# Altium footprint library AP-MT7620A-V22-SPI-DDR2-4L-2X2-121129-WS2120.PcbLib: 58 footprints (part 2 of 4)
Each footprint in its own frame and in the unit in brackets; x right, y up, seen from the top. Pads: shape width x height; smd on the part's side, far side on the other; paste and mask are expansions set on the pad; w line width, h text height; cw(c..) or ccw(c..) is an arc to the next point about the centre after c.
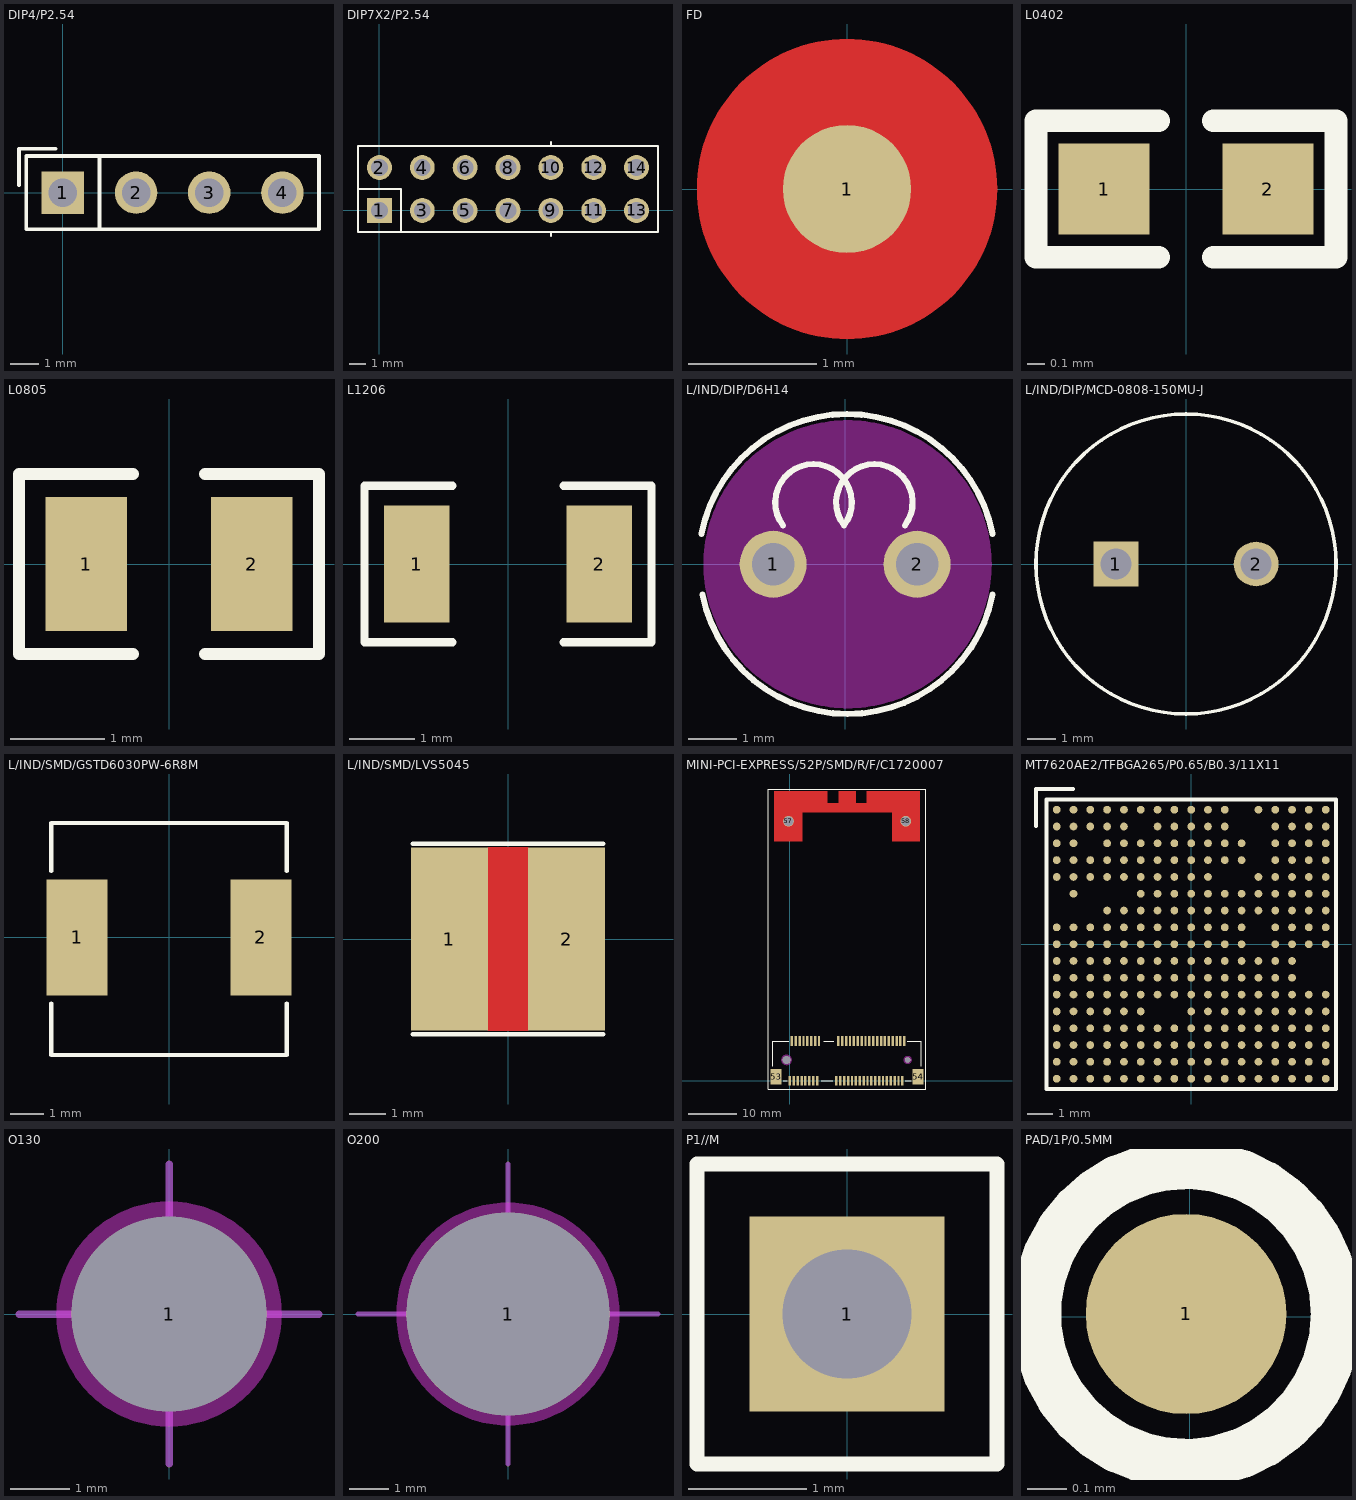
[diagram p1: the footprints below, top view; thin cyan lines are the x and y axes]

## DIP4/P2.54 [mil]
pads (4):
  rect 58x58 hole 39: 1(0,0)
  round 58 hole 39: 2(100,0) 3(200,0) 4(300,0)
Top Overlay:
  lines w5: -60,10 -60,60 -10,60 ; 50,-50 50,50 ; -50,-50 350,-50 350,50 -50,50 -50,-50

## DIP7X2/P2.54 [mil]
pads (14):
  rect 58x58 hole 39: 1(0,0)
  round 58 hole 39: 2(0,100) 3(100,0) 4(100,100) 5(200,0) 6(200,100) 7(300,0) 8(300,100) 9(400,0) 10(400,100) 11(500,0) 12(500,100) 13(600,0) 14(600,100)
Top Overlay:
  lines w5: -50,50 50,50 50,-50 ; 400,-60 400,-50 ; 400,150 400,160 ; -50,-50 650,-50 650,150 -50,150 -50,-50

## FD [mm]
pads (1):
  round 1 smd: 1(0,0)
Top Layer:
  pour cut-out: 1.169,0 1.167,0.057 1.163,0.115 1.156,0.171 1.146,0.228 1.134,0.284 1.118,0.339 1.1,0.394 1.08,0.447 1.057,0.5 1.031,0.551 1.002,0.601 0.972,0.649 0.939,0.696 0.903,0.741 0.866,0.785 0.826,0.826 0.785,0.866 0.741,0.903 0.696,0.939 0.649,0.972 0.601,1.002 0.551,1.031 0.5,1.057 0.447,1.08 0.394,1.1 0.339,1.118 0.284,1.134 0.228,1.146 0.171,1.156 0.115,1.163 0.057,1.167 0,1.169 -0.057,1.167 -0.115,1.163 -0.171,1.156 -0.228,1.146 -0.284,1.134 -0.339,1.118 -0.394,1.1 -0.447,1.08 -0.5,1.057 -0.551,1.031 -0.601,1.002 -0.649,0.972 -0.696,0.939 -0.741,0.903 -0.785,0.866 -0.826,0.826 -0.866,0.785 -0.903,0.741 -0.939,0.696 -0.972,0.649 -1.002,0.601 -1.031,0.551 -1.057,0.5 -1.08,0.447 -1.1,0.394 -1.118,0.339 -1.134,0.284 -1.146,0.228 -1.156,0.171 -1.163,0.115 -1.167,0.057 -1.169,0 -1.167,-0.057 -1.163,-0.115 -1.156,-0.171 -1.146,-0.228 -1.134,-0.284 -1.118,-0.339 -1.1,-0.394 -1.08,-0.447 -1.057,-0.5 -1.031,-0.551 -1.002,-0.601 -0.972,-0.649 -0.939,-0.696 -0.903,-0.741 -0.866,-0.785 -0.826,-0.826 -0.785,-0.866 -0.741,-0.903 -0.696,-0.939 -0.649,-0.972 -0.601,-1.002 -0.551,-1.031 -0.5,-1.057 -0.447,-1.08 -0.394,-1.1 -0.339,-1.118 -0.284,-1.134 -0.228,-1.146 -0.171,-1.156 -0.115,-1.163 -0.057,-1.167 0,-1.169 0.057,-1.167 0.115,-1.163 0.171,-1.156 0.228,-1.146 0.284,-1.134 0.339,-1.118 0.394,-1.1 0.447,-1.08 0.5,-1.057 0.551,-1.031 0.601,-1.002 0.649,-0.972 0.696,-0.939 0.741,-0.903 0.785,-0.866 0.826,-0.826 0.866,-0.785 0.903,-0.741 0.939,-0.696 0.972,-0.649 1.002,-0.601 1.031,-0.551 1.057,-0.5 1.08,-0.447 1.1,-0.394 1.118,-0.339 1.134,-0.284 1.146,-0.228 1.156,-0.171 1.163,-0.115 1.167,-0.057
Top Solder:
  region: 1.016,0 1.015,0.053 1.011,0.106 1.004,0.159 0.994,0.211 0.982,0.263 0.967,0.314 0.949,0.364 0.928,0.413 0.906,0.461 0.88,0.508 0.852,0.554 0.822,0.597 0.79,0.64 0.755,0.68 0.719,0.719 0.68,0.755 0.64,0.79 0.597,0.822 0.554,0.852 0.508,0.88 0.461,0.906 0.413,0.928 0.364,0.949 0.314,0.967 0.263,0.982 0.211,0.994 0.159,1.004 0.106,1.011 0.053,1.015 0,1.016 -0.053,1.015 -0.106,1.011 -0.159,1.004 -0.211,0.994 -0.263,0.982 -0.314,0.967 -0.364,0.949 -0.413,0.928 -0.461,0.906 -0.508,0.88 -0.554,0.852 -0.597,0.822 -0.64,0.79 -0.68,0.755 -0.719,0.719 -0.755,0.68 -0.79,0.64 -0.822,0.597 -0.852,0.554 -0.88,0.508 -0.906,0.461 -0.928,0.413 -0.949,0.364 -0.967,0.314 -0.982,0.263 -0.994,0.211 -1.004,0.159 -1.011,0.106 -1.015,0.053 -1.016,0 -1.015,-0.053 -1.011,-0.106 -1.004,-0.159 -0.994,-0.211 -0.982,-0.263 -0.967,-0.314 -0.949,-0.364 -0.928,-0.413 -0.906,-0.461 -0.88,-0.508 -0.852,-0.554 -0.822,-0.597 -0.79,-0.64 -0.755,-0.68 -0.719,-0.719 -0.68,-0.755 -0.64,-0.79 -0.597,-0.822 -0.554,-0.852 -0.508,-0.88 -0.461,-0.906 -0.413,-0.928 -0.364,-0.949 -0.314,-0.967 -0.263,-0.982 -0.211,-0.994 -0.159,-1.004 -0.106,-1.011 -0.053,-1.015 0,-1.016 0.053,-1.015 0.106,-1.011 0.159,-1.004 0.211,-0.994 0.263,-0.982 0.314,-0.967 0.364,-0.949 0.413,-0.928 0.461,-0.906 0.508,-0.88 0.554,-0.852 0.597,-0.822 0.64,-0.79 0.68,-0.755 0.719,-0.719 0.755,-0.68 0.79,-0.64 0.822,-0.597 0.852,-0.554 0.88,-0.508 0.906,-0.461 0.928,-0.413 0.949,-0.364 0.967,-0.314 0.982,-0.263 0.994,-0.211 1.004,-0.159 1.011,-0.106 1.015,-0.053

## L0402 [mil]
pads (2):
  rect 20x20 smd: 1(-18,0) 2(18,0)
Top Overlay:
  lines w5: -6,-15 -33,-15 -33,15 -6,15 ; 6,-15 33,-15 33,15 6,15

## L0805 [mil]
pads (2):
  rect 34x56 smd: 1(-34.45,0) 2(34.45,0)
Top Overlay:
  lines w5: -15,-37.5 -62.5,-37.5 -62.5,37.5 -15,37.5 ; 15,-37.5 62.5,-37.5 62.5,37.5 15,37.5

## L1206 [mm]
pads (2):
  rect 1x1.8 smd: 1(-1.4,0) 2(1.4,0)
Top Overlay:
  lines w0.127: -0.85,-1.2 -2.2,-1.2 -2.2,1.2 -0.85,1.2 ; 0.85,-1.2 2.2,-1.2 2.2,1.2 0.85,1.2

## L/IND/DIP/D6H14 [mil]
pads (2):
  round 55 hole 35: 1(-59.06,0) 2(59.06,0)
Top Overlay:
  lines w5: -118,25 cw(c1.5,1.55) 121,25 ; -117,-25 ccw(c2,-1.65) 121,-25 ; -63,15 -48,15 ; -51,31.82 cw(c-26,50.79) -1,31.82 cw(c24,50.79) 49,31.82 ; 52,15 67,15
Keep-Out Layer:
  drawing of 1 lines, arcs and shapes, not listed

## L/IND/DIP/MCD-0808-150MU-J [mm]
pads (2):
  rect 1.6x1.6 hole 1.1: 1(-2.5,0)
  round 1.6 hole 1.1: 2(2.5,0)
Top Overlay:
  circle w0.127: c0,0 r5.35

## L/IND/SMD/GSTD6030PW-6R8M [mm]
pads (2):
  rect 1.85x3.5 smd: 1(-2.775,0) 2(2.775,0)
Top Overlay:
  lines w0.127: -3.55,-2 -3.55,-3.55 3.55,-3.55 3.55,-2 ; -3.55,2 -3.55,3.45 3.55,3.45 3.55,2

## L/IND/SMD/LVS5045 [mm]
pads (2):
  rect 2.1x5 smd: 1(-1.6,0) 2(1.6,0)
Top Layer:
  pour cut-out: -0.556,2.507 0.551,2.507 0.551,-2.504 -0.556,-2.504
Top Overlay:
  lines w0.127: -2.6,-2.6 2.6,-2.6 ; -2.6,2.6 2.6,2.6

## MINI-PCI-EXPRESS/52P/SMD/R/F/C1720007 [mm]
pads (58):
  rect 0.5x2 smd: 1(0,0) 2(0.4,8.2) 3(0.8,0) 4(1.2,8.2) 5(1.6,0) 6(2,8.2) 7(2.4,0) 8(2.8,8.2) 9(3.2,0) 10(3.6,8.2) 11(4,0) 12(4.4,8.2) 13(4.8,0) 14(5.2,8.2) 15(5.6,0) 16(6,8.2) 17(9.6,0) 18(10,8.2) 19(10.4,0) 20(10.8,8.2) 21(11.2,0) 22(11.6,8.2) 23(12,0) 24(12.4,8.2) 25(12.8,0) 26(13.2,8.2) 27(13.6,0) 28(14,8.2) 29(14.4,0) 30(14.8,8.2) 31(15.2,0) 32(15.6,8.2) 33(16,0) 34(16.4,8.2) 35(16.8,0) 36(17.2,8.2) 37(17.6,0) 38(18,8.2) 39(18.4,0) 40(18.8,8.2) 41(19.2,0) 42(19.6,8.2) 43(20,0) 44(20.4,8.2) 45(20.8,0) 46(21.2,8.2) 47(21.6,0) 48(22,8.2) 49(22.4,0) 50(22.8,8.2) 51(23.2,0) 52(23.6,8.2)
  rect 2.3x3.2 smd: 53(-2.85,0.8) 54(26.45,0.8)
  round 1.6 hole 1.6 unplated: 55(-0.7,4.3)
  round 1.1 hole 1.1 unplated: 56(24.3,4.3)
  round 2.2 hole 2: 57(-0.3,53.55)
  round 2.2 / inner round 2.2 / far side round 2 hole 2: 58(23.9,53.55)
Top Layer:
  region: -3.2,49.454 2.515,49.454 2.515,55.397 21.082,55.397 21.082,49.454 26.822,49.454 26.822,59.741 15.824,59.741 15.824,57.252 13.564,57.252 13.564,59.741 10.033,59.741 10.033,57.252 7.747,57.252 7.747,59.741 -3.2,59.741
Top Overlay:
  lines w0.127: -3.5,3 -3.5,8.2 -0.21,8.2 ; -1.365,0 -0.525,0 ; 6.5,0 8.8,0 ; 6.927,8.2 9.079,8.2 ; 23.8,0 25,0 ; 24.2,8.2 27.1,8.2 27.1,3 ; -4.5,-1.7 28,-1.7 28,60.2 -4.5,60.2 -4.5,-1.7
Keep-Out Layer:
  drawing of 2 lines, arcs and shapes, not listed

## MT7620AE2/TFBGA265/P0.65/B0.3/11X11 [mm]
pads (265):
  round 0.3 smd: A1(-5.2,5.2) A2(-4.55,5.2) A3(-3.9,5.2) A4(-3.25,5.2) A5(-2.6,5.2) A6(-1.95,5.2) A7(-1.3,5.2) A8(-0.65,5.2) A9(0,5.2) A10(0.65,5.2) A11(1.3,5.2) A13(2.6,5.2) A14(3.25,5.2) A15(3.9,5.2) A16(4.55,5.2) A17(5.2,5.2) B1(-5.2,4.55) B2(-4.55,4.55) B3(-3.9,4.55) B4(-3.25,4.55) B5(-2.6,4.55) B7(-1.3,4.55) B8(-0.65,4.55) B9(0,4.55) B10(0.65,4.55) B11(1.3,4.55) B14(3.25,4.55) B15(3.9,4.55) B16(4.55,4.55) B17(5.2,4.55) C1(-5.2,3.9) C2(-4.55,3.9) C4(-3.25,3.9) C5(-2.6,3.9) C6(-1.95,3.9) C7(-1.3,3.9) C8(-0.65,3.9) C9(0,3.9) C10(0.65,3.9) C11(1.3,3.9) C12(1.95,3.9) C14(3.25,3.9) C15(3.9,3.9) C16(4.55,3.9) C17(5.2,3.9) D1(-5.2,3.25) D2(-4.55,3.25) D3(-3.9,3.25) D4(-3.25,3.25) D5(-2.6,3.25) D6(-1.95,3.25) D7(-1.3,3.25) D8(-0.65,3.25) D9(0,3.25) D10(0.65,3.25) D11(1.3,3.25) D12(1.95,3.25) D14(3.25,3.25) D15(3.9,3.25) D16(4.55,3.25) D17(5.2,3.25) E1(-5.2,2.6) E2(-4.55,2.6) E3(-3.9,2.6) E4(-3.25,2.6) E5(-2.6,2.6) E6(-1.95,2.6) E7(-1.3,2.6) E8(-0.65,2.6) E9(0,2.6) E10(0.65,2.6) E13(2.6,2.6) E14(3.25,2.6) E15(3.9,2.6) E16(4.55,2.6) E17(5.2,2.6) F2(-4.55,1.95) F6(-1.95,1.95) F7(-1.3,1.95) F8(-0.65,1.95) F9(0,1.95) F10(0.65,1.95) F11(1.3,1.95) F12(1.95,1.95) F13(2.6,1.95) F14(3.25,1.95) F15(3.9,1.95) F16(4.55,1.95) F17(5.2,1.95) G4(-3.25,1.3) G5(-2.6,1.3) G6(-1.95,1.3) G7(-1.3,1.3) G8(-0.65,1.3) G9(0,1.3) G10(0.65,1.3) G11(1.3,1.3) G12(1.95,1.3) G13(2.6,1.3) G14(3.25,1.3) G15(3.9,1.3) G16(4.55,1.3) G17(5.2,1.3) H1(-5.2,0.65) H2(-4.55,0.65) H3(-3.9,0.65) H4(-3.25,0.65) H5(-2.6,0.65) H6(-1.95,0.65) H7(-1.3,0.65) H8(-0.65,0.65) H9(0,0.65) H10(0.65,0.65) H11(1.3,0.65) H12(1.95,0.65) H14(3.25,0.65) H15(3.9,0.65) H16(4.55,0.65) H17(5.2,0.65) J1(-5.2,0) J2(-4.55,0) J3(-3.9,0) J4(-3.25,0) J5(-2.6,0) J6(-1.95,0) J7(-1.3,0) J8(-0.65,0) J9(0,0) J10(0.65,0) J11(1.3,0) J12(1.95,0) J14(3.25,0) J15(3.9,0) J16(4.55,0) J17(5.2,0) K1(-5.2,-0.65) K2(-4.55,-0.65) K3(-3.9,-0.65) K4(-3.25,-0.65) K5(-2.6,-0.65) K6(-1.95,-0.65) K7(-1.3,-0.65) K8(-0.65,-0.65) K9(0,-0.65) K10(0.65,-0.65) K11(1.3,-0.65) K12(1.95,-0.65) K13(2.6,-0.65) K14(3.25,-0.65) K15(3.9,-0.65) L1(-5.2,-1.3) L2(-4.55,-1.3) L3(-3.9,-1.3) L4(-3.25,-1.3) L5(-2.6,-1.3) L6(-1.95,-1.3) L7(-1.3,-1.3) L8(-0.65,-1.3) L9(0,-1.3) L10(0.65,-1.3) L11(1.3,-1.3) L12(1.95,-1.3) L13(2.6,-1.3) L14(3.25,-1.3) L15(3.9,-1.3) M1(-5.2,-1.95) M2(-4.55,-1.95) M3(-3.9,-1.95) M4(-3.25,-1.95) M5(-2.6,-1.95) M6(-1.95,-1.95) M7(-1.3,-1.95) M8(-0.65,-1.95) M9(0,-1.95) M10(0.65,-1.95) M11(1.3,-1.95) M12(1.95,-1.95) M13(2.6,-1.95) M14(3.25,-1.95) M15(3.9,-1.95) M16(4.55,-1.95) M17(5.2,-1.95) N1(-5.2,-2.6) N2(-4.55,-2.6) N3(-3.9,-2.6) N4(-3.25,-2.6) N5(-2.6,-2.6) N6(-1.95,-2.6) N9(0,-2.6) N10(0.65,-2.6) N11(1.3,-2.6) N12(1.95,-2.6) N13(2.6,-2.6) N14(3.25,-2.6) N15(3.9,-2.6) N16(4.55,-2.6) N17(5.2,-2.6) P1(-5.2,-3.25) P2(-4.55,-3.25) P3(-3.9,-3.25) P4(-3.25,-3.25) P5(-2.6,-3.25) P6(-1.95,-3.25) P7(-1.3,-3.25) P8(-0.65,-3.25) P9(0,-3.25) P10(0.65,-3.25) P11(1.3,-3.25) P12(1.95,-3.25) P13(2.6,-3.25) P14(3.25,-3.25) P15(3.9,-3.25) P16(4.55,-3.25) P17(5.2,-3.25) R1(-5.2,-3.9) R2(-4.55,-3.9) R3(-3.9,-3.9) R4(-3.25,-3.9) R5(-2.6,-3.9) R6(-1.95,-3.9) R7(-1.3,-3.9) R8(-0.65,-3.9) R9(0,-3.9) R10(0.65,-3.9) R11(1.3,-3.9) R12(1.95,-3.9) R13(2.6,-3.9) R14(3.25,-3.9) R15(3.9,-3.9) R16(4.55,-3.9) R17(5.2,-3.9) T1(-5.2,-4.55) T2(-4.55,-4.55) T3(-3.9,-4.55) T4(-3.25,-4.55) T5(-2.6,-4.55) T6(-1.95,-4.55) T7(-1.3,-4.55) T8(-0.65,-4.55) T9(0,-4.55) T10(0.65,-4.55) T11(1.3,-4.55) T12(1.95,-4.55) T13(2.6,-4.55) T14(3.25,-4.55) T15(3.9,-4.55) T16(4.55,-4.55) T17(5.2,-4.55) U1(-5.2,-5.2) U2(-4.55,-5.2) U3(-3.9,-5.2) U4(-3.25,-5.2) U5(-2.6,-5.2) U6(-1.95,-5.2) U7(-1.3,-5.2) U8(-0.65,-5.2) U9(0,-5.2) U10(0.65,-5.2) U11(1.3,-5.2) U12(1.95,-5.2) U13(2.6,-5.2) U14(3.25,-5.2) U15(3.9,-5.2) U16(4.55,-5.2) U17(5.2,-5.2)
Top Overlay:
  lines w0.152: -6,4.572 -6,6 -4.572,6 ; -5.6,-5.6 5.6,-5.6 5.6,5.6 -5.6,5.6 -5.6,-5.6

## O130 [mil]
pads (1):
  round 130 hole 130 unplated: 1(0,0)
Keep-Out Layer:
  drawing of 1 lines, arcs and shapes, not listed
Mechanical 16:
  lines w5: -100,0 100,0 ; 0,-100 0,100

## O200 [mil]
pads (1):
  round 203 hole 203 unplated: 1(0,0)
Keep-Out Layer:
  drawing of 1 lines, arcs and shapes, not listed
Mechanical 16:
  lines w5: -150,0 150,0 ; 0,-150 0,150

## P1//M [mil]
pads (1):
  rect 65x65 hole 43: 1(0,0)
Top Overlay:
  lines w5: -50,-50 50,-50 50,50 -50,50 -50,-50

## PAD/1P/0.5MM [mil]
pads (1):
  round 20 smd: 1(-0.39,0.26)
Top Overlay:
  circle w5: c-0.4,0.26 r14.96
